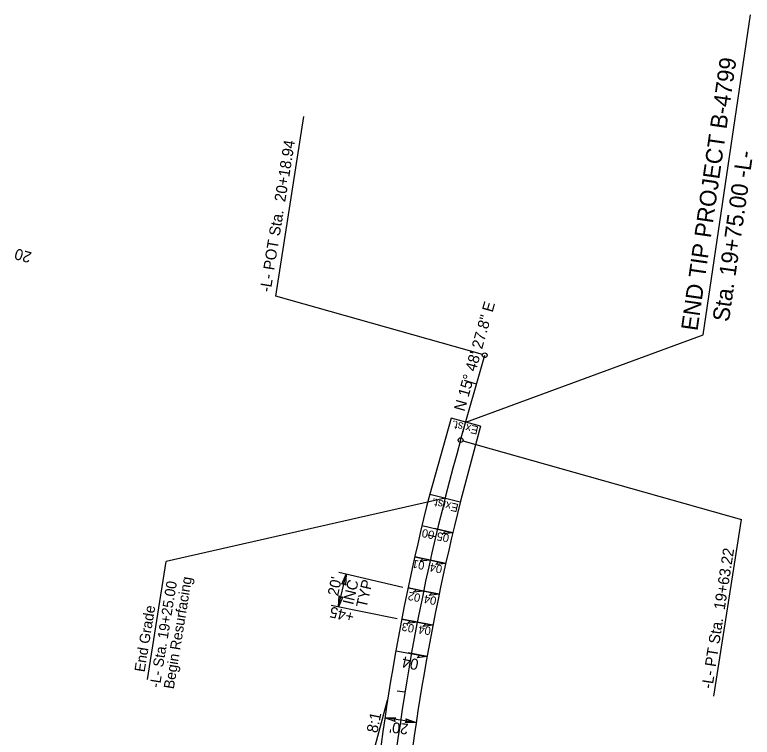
# Model space of a CAD drawing. Extents: x 1698814 to 1699654, y 708133 to 709468.
# Drawn here: x 1699188.3 to 1699653.8, y 709011.7 to 709468.1 of the extents above; entities that cross this region are included whole.
import ezdxf

# ---------------------------------------------------------------- set-up
doc = ezdxf.new("R2010")
doc.units = 0
for name, color, linetype in [('Prop Dimension', 7, 'Continuous'), ('Prop EOT', 7, 'Continuous'), ('Prop Horizontal Alignment', 7, 'Continuous'), ('Prop Horizontal Alignment Curve and Spiral Data', 7, 'Continuous'), ('Prop Horizontal Alignment Direction Label', 7, 'Continuous'), ('Prop Horizontal Alignment Station Label', 7, 'Continuous'), ('Prop Horizontal Alignment Tick Label', 7, 'Continuous'), ('Prop Horizontal Alignment Tick Large', 7, 'Continuous'), ('Prop Horizontal Alignment Tick Small', 7, 'Continuous'), ('Prop Paved Shoulder', 7, 'Continuous'), ('Prop Superelevation  Arrow CELL', 7, 'Continuous'), ('Prop Superelevation Label', 7, 'Continuous'), ('Prop Terminator CELL', 7, 'Continuous')]:
    doc.layers.add(name, color=color, linetype=linetype)

msp = doc.modelspace()

# ---------------------------------------------------------------- linework, layer by layer
at = {"layer": 'Prop Dimension'}
for p, q in [((1699482.24, 709208.11), (1699463.75, 709213.35)), ((1699459.95, 709162.77), (1699283.92, 709122.8)), ((1699272.04, 709048.2), (1699283.92, 709122.8)), ((1699392.68, 709094.17), (1699397.42, 709114.65)), ((1699388.03, 709095.1), (1699429.81, 709086.7)), ((1699441.73, 709020.98), (1699421.95, 709023.9))]:
    msp.add_line(p, q, dxfattribs=at)
at = {"layer": 'Prop EOT'}
for p, q in [((1699463.75, 709213.35), (1699450.26, 709165.23)), ((1699482.24, 709208.11), (1699469.75, 709160.74))]:
    msp.add_line(p, q, dxfattribs=at)
for radius, start in [(1410, 165.74431), (1390, 165.7259)]:
    msp.add_arc((1700816.84, 708818.02), radius, start, 176.20849, dxfattribs=at)
at = {"layer": 'Prop Horizontal Alignment'}
msp.add_line((1699469.78, 709199.39), (1699484.96, 709253), dxfattribs=at)
msp.add_arc((1700816.84, 708818.02), 1400, 164.19229, 176.20849, dxfattribs=at)
at = {"layer": 'Prop Horizontal Alignment Station Label'}
for p, q in [((1699622.84, 709265.9), (1699652.73, 709468.05)), ((1699353.11, 709290.33), (1699370.86, 709403.79)), ((1699483.52, 709253.41), (1699353.11, 709290.33)), ((1699472.99, 709210.73), (1699622.84, 709265.9)), ((1699471.23, 709198.98), (1699647.07, 709149.2)), ((1699629.62, 709037.63), (1699647.07, 709149.2))]:
    msp.add_line(p, q, dxfattribs=at)
for centre in [(1699484.96, 709253), (1699469.78, 709199.39)]:
    msp.add_circle(centre, 1.5, dxfattribs=at)
at = {"layer": 'Prop Horizontal Alignment Tick Large'}
msp.add_line((1699479.8, 709234.78), (1699472.11, 709236.96), dxfattribs=at)
at = {"layer": 'Prop Horizontal Alignment Tick Small'}
for p, q in [((1699453.94, 709138.2), (1699449.07, 709139.34)), ((1699434.57, 709040.11), (1699429.63, 709040.91))]:
    msp.add_line(p, q, dxfattribs=at)
at = {"layer": 'Prop Paved Shoulder'}
msp.add_line((1699413.6, 708997.95), (1699423.64, 709035.08), dxfattribs=at)
at = {"layer": 'Prop Superelevation  Arrow CELL'}
for p, q in [((1699464.84, 709140.84), (1699453.17, 709143.62)), ((1699450.59, 709123.58), (1699440.81, 709125.69)), ((1699460.36, 709121.46), (1699448.63, 709124)), ((1699446.37, 709104.04), (1699436.58, 709106.09)), ((1699456.16, 709102), (1699444.41, 709104.45)), ((1699442.42, 709084.42), (1699432.58, 709086.22)), ((1699452.25, 709082.62), (1699440.45, 709084.78)), ((1699448.56, 709062.82), (1699436.75, 709064.94))]:
    msp.add_line(p, q, dxfattribs=at)
for points in [[(1699464.84, 709140.84), (1699458.54, 709140.29), (1699460.34, 709141.91)], [(1699450.59, 709123.58), (1699444.3, 709122.89), (1699446.07, 709124.55)], [(1699460.36, 709121.46), (1699454.08, 709120.78), (1699455.84, 709122.44)], [(1699446.37, 709104.04), (1699440.08, 709103.31), (1699441.84, 709104.99)], [(1699456.16, 709102), (1699449.87, 709101.27), (1699451.63, 709102.95)], [(1699442.42, 709084.42), (1699436.16, 709083.53), (1699437.87, 709085.25)], [(1699452.25, 709082.62), (1699445.99, 709081.73), (1699447.71, 709083.45)], [(1699448.56, 709062.82), (1699442.31, 709061.91), (1699444.01, 709063.64)]]:
    msp.add_lwpolyline(points, close=True, dxfattribs=at)
at = {"layer": 'Prop Superelevation Label'}
for p, q in [((1699450.26, 709165.23), (1699469.44, 709160.37)), ((1699445.39, 709145.48), (1699464.84, 709140.84)), ((1699440.81, 709125.69), (1699460.36, 709121.46)), ((1699433.19, 709106.38), (1699392.8, 709115.72)), ((1699436.58, 709106.09), (1699456.16, 709102)), ((1699432.58, 709086.22), (1699452.25, 709082.62)), ((1699428.88, 709066.35), (1699448.56, 709062.82))]:
    msp.add_line(p, q, dxfattribs=at)
at = {"layer": 'Prop Terminator CELL'}
for points in [[(1699394.82, 709108.31), (1699397.42, 709114.65), (1699397.12, 709107.76), (1699396.14, 709108.87)], [(1699395.42, 709100.45), (1699392.68, 709094.17), (1699393.13, 709101.05), (1699394.09, 709099.92)], [(1699428.44, 709021.7), (1699421.95, 709023.9), (1699428.84, 709024.03), (1699427.8, 709022.98)], [(1699435.28, 709023.28), (1699441.73, 709020.98), (1699434.84, 709020.96), (1699435.9, 709022)]]:
    msp.add_lwpolyline(points, close=True, dxfattribs=at)

# ---------------------------------------------------------------- texts
at = {"layer": 'Prop Dimension'}
for s, height, rotation, p in [('Begin Resurfacing', 6.5625, 80.7477, (1699288.7, 709041.86)), ("20'", 6.825, 78.0731, (1699392.38, 709100.54)), ('-L- Sta. 19+25.00', 6.5625, 80.7477, (1699279.84, 709042.65)), ('INC', 6.825, 76.9845, (1699401.89, 709095.02)), ('TYP', 6.825, 76.9845, (1699410.32, 709093.08)), ('End Grade', 6.562, 80.7477, (1699270.26, 709052.58)), ('+45', 6.825, 166.1917, (1699403.14, 709090.67)), ('8:1', 7, 78.3599, (1699417.15, 709014.04)), ("20'", 6.825, 173.2942, (1699437.07, 709020.12))]:
    msp.add_text(s, height=height, rotation=rotation, dxfattribs=at).set_placement(p)
at = {"layer": 'Prop Horizontal Alignment Curve and Spiral Data'}
for s, p in [('END TIP PROJECT B-4799', (1699619.22, 709268.01)), ('Sta. 19+75.00 -L-', (1699639.09, 709273.72))]:
    msp.add_text(s, height=10.5, rotation=81.8272, dxfattribs=at).set_placement(p)
at = {"layer": 'Prop Horizontal Alignment Direction Label'}
msp.add_text('N 15%%d 48\' 27.8" E', height=7, rotation=74.1923, dxfattribs=at).set_placement((1699472.15, 709217.12))
at = {"layer": 'Prop Horizontal Alignment Station Label'}
for s, rotation, p in [('-L- POT Sta.  20+18.94', 80.8217, (1699349.81, 709292.49)), ('-L- PT Sta.  19+63.22', 81.1123, (1699628.61, 709041.99))]:
    msp.add_text(s, height=7, rotation=rotation, dxfattribs=at).set_placement(p)
at = {"layer": 'Prop Horizontal Alignment Tick Label'}
msp.add_text('20', height=7, rotation=164.1923, dxfattribs=at).set_placement((1699199.44, 709317.8))
at = {"layer": 'Prop Superelevation Label'}
for s, height, rotation, p in [('Exist.', 5.25, 166.7294, (1699481.41, 709207.93)), ('Exist.', 5.25, 166.7294, (1699468.8, 709158.89)), ('00', 5.25, 168.3505, (1699453.56, 709141.84)), ('05', 5.25, 168.3505, (1699462.94, 709139.83)), ('01', 5.25, 168.3505, (1699447.4, 709122.47)), ('04', 5.25, 168.3505, (1699458.56, 709120.2)), ('02', 5.25, 168.3505, (1699444.76, 709102.1)), ('04', 5.25, 168.3505, (1699454.87, 709100.21)), ('03', 5.25, 168.3505, (1699440.87, 709082.71)), ('04', 5.25, 172.2665, (1699451.28, 709081.37)), ('04', 7, 168.3505, (1699443.74, 709060.81))]:
    msp.add_text(s, height=height, rotation=rotation, dxfattribs=at).set_placement(p)

doc.saveas('drawing.dxf')
